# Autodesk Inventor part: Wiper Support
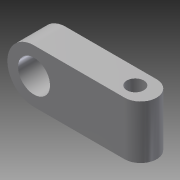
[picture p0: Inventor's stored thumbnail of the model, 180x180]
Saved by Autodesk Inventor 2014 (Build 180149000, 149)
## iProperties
Created: 2006-03
Part Number: Wiper Support
Document SubType Name: Modeling
Designer: debonom
Material: Stainless Steel, 440C
Mass: 138.885 g
Surface Area: 61.269 cm^2
Volume: 17.9206 cm^3
Density: 7.75 g/cm^3
Appearance: Steel
Author: debonom
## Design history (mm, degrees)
sketch "Sketch1"
  geometry: L1 (-37.5, 0)-(50, 0) reference; L2 (25, 12.5)-(-25, 12.5); L3 (-25, 12.5)-(-25, -12.5); L4 (-25, -12.5)-(25, -12.5); L5 (25, -12.5)-(25, 12.5); L6 (25, 12.5)-(-25, -12.5); A1 r 12.5 centre (25, 0) between (25, -12.5) and (25, 12.5); 1 further point
  constraints: 10 end point, 2 midpoint, 2 parallel, 2 point on circle, 1 centre point, 1 horizontal, 1 perpendicular, 1 point on line
  dimensions: "d11" = 25 distance of L4.end L2.start; "d12" = 50 distance of L2.start L2.end
extrude "Extrusion1" new body sketch "Sketch1" stored distance "d3" = 15; taper "d4" = 0 deg
sketch "Sketch4"
  geometry: C1 r 7.5 at (25, 0); A1 r 12.5 centre (25, 0) between (25, -12.5) and (25, 12.5) reference; 1 further point
  constraints: 1 centre point, 1 coincident
  dimensions: "d13" = 15 diameter of C1
extrude "Extrusion3" cut sketch "Sketch4" stored distance "d14" = 15; taper "d15" = 0 deg
sketch "Sketch3"
  geometry: L1 (-5, 0)-(30, 0) reference; L2 (25, -7.5)-(25, 7.5) reference; C1 r 4 at (15, 0); 1 further point
  constraints: 1 centre point, 1 point on line
  dimensions: "d8" = 8 diameter of C1; "d16" = 10 distance from line of L2 C1.centre
extrude "Extrusion2" cut sketch "Sketch3" stored distance "d9" = 15; taper "d10" = 0 deg
fillet "Fillet2"
body "Solid1"
